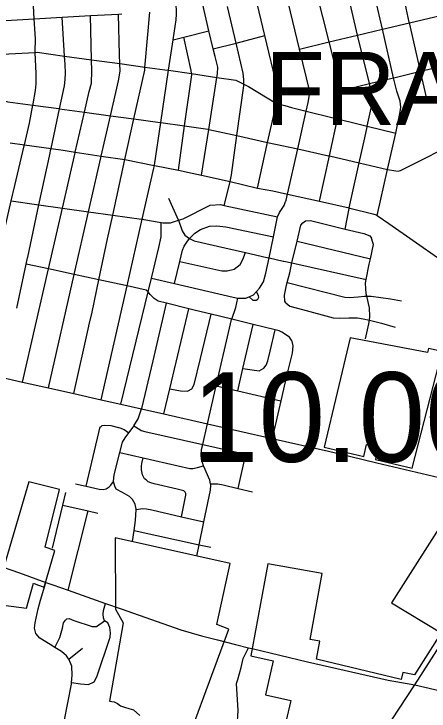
# Model space of a CAD drawing. Extents: x 1659811 to 1934326, y 644115 to 934867.
# Drawn here: x 1806134 to 1811230, y 699875 to 708432 of the extents above; entities that cross this region are included whole.
import ezdxf

# ---------------------------------------------------------------- set-up
doc = ezdxf.new("R2010")
doc.units = 0
for name, color, linetype in [('Default', 7, 'Continuous'), ('GM_X_City_Street', 7, 'Continuous'), ('GM_X_Corporation', 7, 'Continuous'), ('GM_X_County_Road', 7, 'Continuous'), ('GM_X_Township_Text', 7, 'Continuous'), ('GM_X_US_Route', 7, 'Continuous')]:
    doc.layers.add(name, color=color, linetype=linetype)

msp = doc.modelspace()

# ---------------------------------------------------------------- linework, layer by layer
at = {"layer": 'GM_X_City_Street'}
for points in [[(1809469.5, 706130), (1809470.5, 706132.6), (1809476.6, 706148), (1809493.1, 706221), (1809618.1, 706774.9), (1809722.9, 707239), (1809747.3, 707347.2), (1809763.4, 707438), (1809764.4, 707482.2), (1809638.9, 708001.1), (1809446.6, 708801.4), (1809436.2, 708962.9), (1809402, 709522.5), (1809362.2, 710340.5), (1809325.9, 711086.3), (1809295.4, 711711.7), (1809260.4, 712456.7), (1809250.3, 712638.9)], [(1810250.2, 706050.6), (1810371.9, 706604.5), (1810439.5, 706912.4), (1810468.3, 707047.1), (1810469.8, 707053.9), (1810526, 707312.5), (1810531.5, 707368.8), (1810529, 707430.9), (1810507.9, 707539.1), (1810498.6, 707577), (1810352.9, 708171.1), (1810167.1, 708970.7), (1810118.9, 709562.3), (1810067.6, 710366.2), (1810067.4, 710370.1), (1810046.9, 711172.8), (1810010.5, 711774.3), (1809977.9, 712491.9), (1809970.4, 712682.5)], [(1808130, 708430.2), (1808130.8, 708488), (1808122.4, 708568.2), (1808073, 709447.5), (1808038.1, 710255.1), (1808036.4, 710292.2), (1808003.3, 711024.4), (1807975.6, 711638.4), (1807936.9, 712341.2), (1807933.8, 712562.4)], [(1809885.1, 706132.7), (1810005.7, 706689.6), (1810104.2, 707144.5), (1810142.7, 707322.1), (1810155.4, 707432.2), (1810151.8, 707493.4), (1810151.1, 707504.5), (1810005.5, 708088.4), (1809848.5, 708706.8), (1809807.8, 708886.5), (1809793, 709106.1), (1809765.2, 709542.6), (1809723.4, 710336.8), (1809723.1, 710343.3)], [(1809638.9, 708001.1), (1810005.5, 708088.4), (1810352.9, 708171.1), (1810658.7, 708243.9), (1810988, 708322.3), (1811300, 708396.6), (1811615.4, 708471.7), (1812093.2, 708585.5), (1812657.1, 708719.7), (1812940.3, 708787.1), (1813257.9, 708862.8), (1813551, 708932.5), (1813844.2, 709002.4), (1814122.3, 709068.6), (1814126.3, 709069.6), (1814407, 709145.9), (1814414.6, 709147.5), (1814436, 709152.1)], [(1811203.3, 707388.4), (1811125, 707728), (1810988, 708322.3), (1810985.6, 708332.8), (1810949.7, 708504.3), (1810927.3, 708657.3), (1810892.8, 708856.1), (1810837.3, 709094.8), (1810829.4, 709130.4), (1810828.6, 709139.1)], [(1806382.7, 708373.8), (1806361.9, 708776.6)], [(1809121.8, 706294.3), (1809248.6, 706853.5), (1809356.4, 707334.5), (1809379.2, 707446.5), (1809378.8, 707472.2), (1809365.4, 707539.5), (1809213.8, 708167.7), (1809098.6, 708650.1), (1809088, 708689.4), (1809081.8, 708712.6)], [(1810591.1, 705958.6), (1810719.6, 706523.8), (1810820.5, 706967), (1810875.4, 707231.5), (1810884.9, 707287.8), (1810876.3, 707359.9), (1810835.1, 707483.9), (1810804, 707598), (1810792.7, 707647.9), (1810658.7, 708243.9), (1810574.3, 708619.2)], [(1808436.7, 706454.3), (1808525.4, 707014.8), (1808626.6, 707654.1), (1808633.6, 707698.3), (1808635.6, 707778.5), (1808604.7, 707911.6), (1808581.5, 708005.2), (1808527.1, 708224.5), (1808448.1, 708562.7), (1808446.4, 708569.5)], [(1808713.5, 706082.1), (1808787.7, 706370.1), (1808789, 706376.8), (1808803.9, 706456), (1808870.5, 706939.2), (1808954.9, 707551.9), (1808955.4, 707571), (1808956.8, 707628.1), (1808948.7, 707706.6), (1808863, 708074.4), (1808755.6, 708524.3)], [(1807606, 707144.2), (1807606, 707144.2), (1807739.8, 707741.9), (1807742.3, 707781.1), (1807744.7, 707818), (1807802.7, 708452.9)], [(1802838.7, 708169.5), (1802858.4, 708170.7), (1803206.5, 708189.8), (1803531.1, 708211.5), (1803858.4, 708229.7), (1804775.1, 708283.5), (1805404.4, 708317.3), (1805677, 708333), (1805867.1, 708344.3), (1806036.3, 708353.8), (1806382.7, 708373.8), (1806727.9, 708392.6), (1807075.3, 708413.2), (1807419.1, 708431.3), (1807458.3, 708433.7)], [(1806369.5, 707328.4), (1806399.7, 707490.7), (1806408.7, 707572.8), (1806406.2, 707703.2), (1806393.4, 707960.1), (1806393.2, 707966), (1806396.8, 708127.3), (1806382.7, 708373.8)], [(1806577.3, 706724.3), (1806584.1, 706755.9), (1806589.3, 706780), (1806694.3, 707269.6), (1806754.8, 707551.7), (1806764.6, 707625.7), (1806766.5, 707703.9), (1806761.1, 707812.4), (1806754.4, 707915.8), (1806727.9, 708392.6)], [(1806884.5, 706726.4), (1806884.6, 706726.7), (1806886.8, 706736.4), (1806999.5, 707227.6), (1807057.9, 707482), (1807084.5, 707583.7), (1807090.2, 707736.1), (1807086.2, 707870.5), (1807075.3, 708413.2)], [(1807200.9, 706667.1), (1807201.8, 706670.7), (1807205.7, 706688.1), (1807318.6, 707183.7), (1807416.1, 707611.7), (1807439, 707729.6), (1807435.7, 707822.9), (1807431.9, 707932.4), (1807419.1, 708431.3)], [(1807852, 706541.4), (1807858.9, 706571.8), (1807860.2, 706577.5), (1807937.3, 707098.6), (1808032.5, 707741.1), (1808087.9, 708115.5), (1808124.3, 708360.9), (1808129.9, 708429), (1808130, 708430.2)], [(1808087.9, 708115.5), (1808220.1, 708148.3), (1808527.1, 708224.5)], [(1808153.6, 706513.2), (1808229.3, 707057.4), (1808316.4, 707684), (1808313.8, 707699.9), (1808307.7, 707738.3), (1808220.1, 708148.3)], [(1808581.5, 708005.2), (1808863, 708074.4), (1809213.8, 708167.7)], [(1810814.6, 707653.2), (1810815.1, 707653.3), (1811125, 707728), (1811442.4, 707804.6), (1811753.4, 707879.6), (1812224, 707993), (1812752.1, 708120.3)], [(1805707.8, 707925.6), (1806072.4, 707944), (1806393.4, 707960.1), (1806419.3, 707961.4), (1806754.4, 707915.8), (1807086.2, 707870.5), (1807435.7, 707822.9), (1807742.3, 707781.1), (1807987.9, 707747.6), (1808032.5, 707741.1), (1808313.8, 707699.9), (1808626.6, 707654.1), (1808855.9, 707620.5), (1808955.4, 707571), (1809014.3, 707541.7), (1809356.4, 707334.5), (1809461.1, 707306.7), (1809539.9, 707284.3), (1809722.9, 707239), (1810050.9, 707157.7), (1810060.6, 707155.3)], [(1810151.8, 707493.4), (1810498.6, 707577), (1810792.7, 707647.9), (1810814.6, 707653.2)], [(1804712.6, 707421.2), (1805304.8, 707430.5), (1805701.8, 707436.7), (1805729, 707435.6), (1805784, 707433.4), (1806058.5, 707353.2), (1806366.4, 707312.8)], [(1806260, 706815.5), (1806262.6, 706826.4), (1806325.1, 707090.5), (1806366.6, 707312.8), (1806369.1, 707326.5), (1806369.5, 707328.4)], [(1807606, 707144.2), (1807927.1, 707100), (1807937.3, 707098.6), (1808229.3, 707057.4), (1808514.9, 707017.1), (1808525.4, 707014.8), (1808870.5, 706939.2), (1809248.6, 706853.5), (1809618.1, 706774.9), (1809996.7, 706691.7), (1810005.7, 706689.6), (1810371.9, 706604.5), (1810719.6, 706523.8), (1810819.9, 706506.6), (1810850, 706502.9), (1810880, 706511.2), (1811659, 706904.2), (1811962.6, 707005.7), (1812095.4, 707050.1), (1812427.5, 707165.1), (1812952.3, 707346.9)], [(1806366.4, 707312.8), (1806366.6, 707312.8), (1806366.6, 707312.8), (1806683.2, 707271.2), (1806694.3, 707269.6), (1806999.5, 707227.6), (1807318.6, 707183.7), (1807606, 707144.2)], [(1810060.6, 707155.3), (1810104.2, 707144.5), (1810357.4, 707081.8), (1810469.8, 707053.9), (1810820.5, 706967)], [(1807055.1, 704601.7), (1807055.3, 704602.5), (1807093.3, 704773.8), (1807177.3, 705170.5), (1807283.8, 705673.9), (1807346.7, 705963.5), (1807494.7, 706644.4), (1807606, 707144.2)], [(1805948.8, 705487.2), (1806100.3, 706138.1), (1806144.2, 706326.6), (1806259.5, 706813.7), (1806260, 706815.5)], [(1806087.6, 706851.3), (1806262.6, 706826.4), (1806589.3, 706780), (1806737.7, 706758.9), (1806886.8, 706736.4), (1807205.7, 706688.1), (1807494.7, 706644.4)], [(1806239.1, 703913.6), (1806558, 705303.4), (1806729.3, 706050), (1806884.5, 706726.4)], [(1806301.2, 705436.9), (1806303.4, 705447.1), (1806441.3, 706090.3), (1806577.3, 706724.3)], [(1806557.7, 703842.4), (1806874.9, 705235.4), (1807050.2, 706005), (1807200.9, 706667.1)], [(1807494.7, 706644.4), (1807856.6, 706572.3)], [(1807856.6, 706572.3), (1807858.9, 706571.8), (1807859.3, 706571.8), (1808153.6, 706513.2), (1808319.9, 706480), (1808436.7, 706454.3), (1808789, 706376.8), (1809121.8, 706294.3), (1809310.3, 706262.1), (1809493.1, 706221), (1809885.1, 706132.7), (1810250.2, 706050.6), (1810258.7, 706048.6), (1810538.2, 705977.2), (1810582.1, 705964.7), (1810582.7, 705964.3)], [(1807204.5, 703696.9), (1807522.8, 705095.5), (1807708.9, 705912.7), (1807851.9, 706541.2), (1807852, 706541.4)], [(1806099.6, 706138.2), (1806100.3, 706138.1), (1806441.3, 706090.3), (1806729.3, 706050), (1807050.2, 706005), (1807346.7, 705963.5), (1807701.6, 705913.7), (1807708.9, 705912.7), (1807717.2, 705911.5), (1807730.5, 705909.3)], [(1808156, 705899.4), (1808036.7, 706167.8)], [(1809076.7, 704984), (1809110.2, 705024), (1809147.1, 705067.9), (1809195.7, 705143.4), (1809225.4, 705248.5), (1809265.3, 705438.4), (1809319.2, 705695), (1809370.8, 705940.7), (1809395.7, 705995.5), (1809450, 706081.1), (1809469.5, 706130)], [(1807730.5, 705909.3), (1807939.8, 705872.9), (1807963.1, 705868.9), (1808055.4, 705869), (1808156, 705899.4), (1808213, 705916.7), (1808542.5, 706086.8), (1808668.8, 706091.7), (1808713.5, 706082.1), (1809370.8, 705940.7)], [(1810200.2, 705792.3), (1810249.2, 706045.5), (1810250.2, 706050.6)], [(1810582.7, 705964.3), (1810591.1, 705958.6), (1810735, 705860.7), (1811674.4, 705206.2), (1812217.4, 704801.4), (1812401.4, 704707.6), (1812492, 704675.2), (1812669, 704628.6), (1812760.6, 704607.6), (1812860.2, 704584.6)], [(1807446.9, 703641.9), (1807780.7, 705022.8), (1807820.9, 705189.2), (1807911.7, 705564.8), (1807940.9, 705694.6), (1807940.8, 705770.8), (1807939.8, 705872.9)], [(1808156, 705899.4), (1808199.5, 705768.5), (1808232.2, 705715.5), (1808289.5, 705676), (1808346.9, 705646.5), (1808721.9, 705563.1), (1808977.2, 705502.6), (1809236.6, 705444.8), (1809243.9, 705443.2)], [(1809471.5, 704884.5), (1809458, 704906.9), (1809455.8, 704981.2), (1809476.4, 705083.1), (1809489, 705135), (1809518.7, 705256.6), (1809547, 705375.6), (1809610.4, 705642), (1809657.3, 705839.1), (1809680, 705866.7), (1809713.1, 705892.2)], [(1809713.1, 705892.2), (1809775.3, 705897.6), (1810200.2, 705792.3), (1810429.3, 705735.6), (1810502.2, 705709.1), (1810524.9, 705681.5)], [(1808289.5, 705676), (1808353.2, 705740.6), (1808422.5, 705787.1), (1808535.8, 705826.4), (1808626.1, 705830.3), (1808734.1, 705817.6), (1809319.2, 705695)], [(1808103, 705123.8), (1808169.9, 705394.8), (1808203.7, 705531.6), (1808223, 705581.3), (1808256.3, 705632.6), (1808289.5, 705676)], [(1809610.4, 705642), (1810510, 705426.1)], [(1810450.4, 704445.7), (1810490.1, 704626.8), (1810497.3, 704672), (1810504.4, 704716.8), (1810497, 704825.3), (1810465.3, 704968.5), (1810459, 704996.8), (1810448.2, 705127.5), (1810457.4, 705172.6), (1810496, 705361.1), (1810510, 705426.1), (1810548, 705602.6), (1810538.6, 705626.9), (1810524.9, 705681.5)], [(1808169.9, 705394.8), (1808687, 705281), (1808751.1, 705277.4), (1808837.8, 705299.3), (1808909.4, 705357.8), (1808945, 705419.1), (1808977.2, 705502.6)], [(1809243.9, 705443.2), (1809265.3, 705438.4), (1809440, 705399.4), (1809446.1, 705398.1)], [(1806168.7, 704818.9), (1806285.2, 705362), (1806301.2, 705436.9)], [(1808364.7, 704793.7), (1808282.2, 704813.9), (1808008.1, 704881.1), (1807905.7, 704908.8), (1807856.4, 704940.1), (1807805.4, 704987.5), (1807780.7, 705022.8), (1807758.6, 705042.8), (1807522.8, 705095.5), (1807425.5, 705117.2), (1807177.3, 705170.5), (1806874.9, 705235.4), (1806558, 705303.4), (1806285.2, 705362)], [(1809446.1, 705398.1), (1809547, 705375.6), (1810457.4, 705172.6)], [(1807820.9, 705189.2), (1808103, 705123.8), (1808823.4, 704956.6), (1808882.5, 704943.6), (1808979.6, 704944.7), (1809008, 704956.1), (1809022.3, 704961.9), (1809076.7, 704984)], [(1809489, 705135), (1810195.3, 704955.1), (1810247.3, 704949.8), (1810359.8, 704959.1), (1810436.3, 704969.3), (1810465.3, 704968.5), (1810520.5, 704967.2), (1810756.4, 704935.3), (1810890.1, 704912)], [(1809022.3, 704961.9), (1809067.2, 704918.5), (1809109.3, 704917.5), (1809127.7, 704933.1), (1809138.3, 704956.9), (1809134.7, 704973), (1809110.2, 705024)], [(1808377.3, 701777.5), (1808406.5, 701917.8), (1808464.5, 702196.2), (1808546.1, 702587.8), (1808549.7, 702648.1), (1808546, 702666.2), (1808537.2, 702710.3), (1808463.8, 702878.5), (1808461.5, 702885.7), (1808435.1, 702968.6), (1808432.8, 703018.8), (1808438.3, 703087.1), (1808451.4, 703147.6), (1808467.4, 703221.9), (1808509.2, 703401.7), (1808617.1, 703866), (1808806.2, 704680.1), (1808807.9, 704685.2), (1808857.2, 704831), (1808882.5, 704943.6)], [(1807589.4, 701958), (1807608.2, 702089.8), (1807626.3, 702216.3), (1807633.1, 702348.6), (1807633.4, 702352.9), (1807620.9, 702417), (1807588.4, 702471), (1807552.1, 702509), (1807465.5, 702556.6), (1807389, 702600.2), (1807370.7, 702636.3), (1807355.7, 702692.8), (1807354.2, 702698.4), (1807363.7, 702776.8), (1807434.6, 703049.8), (1807467.2, 703175.1), (1807498.9, 703227.5), (1807545.3, 703291), (1807596.2, 703360.7), (1807606.5, 703377.8), (1807657.7, 703463.5), (1807701.4, 703584.3), (1807702.9, 703588.3), (1807843.2, 704175.6), (1808008.1, 704881.1)], [(1809471.5, 704884.5), (1809518.7, 704845.2), (1809674.2, 704805.3), (1810050.7, 704703.8), (1810134.9, 704699.7), (1810243.3, 704703.1), (1810351.5, 704700.4), (1810421.5, 704690.7), (1810497.3, 704672), (1810646.7, 704635), (1810814.1, 704588.8)], [(1807975.4, 703522.2), (1808048.8, 703831.6), (1808282.2, 704813.9)], [(1809421.7, 704526.4), (1809421.3, 704526.6), (1809389, 704541.4), (1809341.2, 704553.7), (1809069.2, 704621.2), (1808807.9, 704685.2), (1808555.1, 704747.1), (1808364.7, 704793.7)], [(1808048.8, 703831.6), (1808177.7, 703806.6), (1808263.8, 703800.5), (1808318.7, 703831.2), (1808346.1, 703884.7), (1808424, 704203.9), (1808555.1, 704747.1)], [(1806871, 703772.4), (1807055.1, 704601.7)], [(1808881.2, 703805.3), (1808944.8, 704081.1), (1809069.2, 704621.2)], [(1808944.8, 704081.1), (1809058.4, 704061.9), (1809142.3, 704051.8), (1809201.3, 704082.5), (1809232.2, 704119.9), (1809249.6, 704173.6), (1809278.6, 704293.3), (1809341.2, 704553.7)], [(1809540.6, 704429.3), (1809515.4, 704464.1), (1809483.9, 704486.9), (1809444.5, 704516), (1809421.7, 704526.4)], [(1809540.6, 704429.3), (1809559, 704358.7), (1809548.8, 704268.6), (1809484.2, 704005.4), (1809409.4, 703683.9), (1809302.1, 703222.6)], [(1804586.6, 704386.7), (1804884.4, 704291.4), (1805625.6, 704054.1), (1806239.1, 703913.6), (1806557.7, 703842.4), (1806871, 703772.4), (1807204.5, 703696.9), (1807446.9, 703641.9), (1807701.4, 703584.3), (1807975.4, 703522.2), (1808509.2, 703401.7), (1809302.1, 703222.6), (1809996.4, 703066.2), (1810269.2, 703000.7), (1810590.2, 702923.5), (1811351.9, 702740.4), (1811573.5, 702687.1), (1812482.7, 702469.2)], [(1808617.1, 703866), (1808881.2, 703805.3), (1809409.4, 703683.9)], [(1807020.3, 702636), (1807193.2, 703364), (1807199.2, 703366.1), (1807217.1, 703380.3)], [(1807217.1, 703380.3), (1807245.1, 703386.5), (1807323.4, 703379), (1807435.9, 703351.6), (1807488.2, 703329.9), (1807545.3, 703291)], [(1807606.5, 703377.8), (1807678.6, 703331.1), (1807694.8, 703319.2), (1807739, 703307.4), (1808451.4, 703147.6), (1808982.1, 703030.5)], [(1807434.6, 703049.8), (1807721.1, 702983.4), (1808291.6, 702851.2), (1808329.7, 702853.5), (1808387.7, 702865.9), (1808461.5, 702885.7)], [(1808192, 702260.4), (1808243.7, 702525.6), (1808243.6, 702547.7), (1808237.5, 702563.7), (1808221.3, 702579.7), (1808139, 702597.2), (1807853.8, 702663.6), (1807813.6, 702675.4), (1807783.4, 702687.2), (1807755.2, 702713.1), (1807735, 702725), (1807710.6, 702773.1), (1807700.2, 702835.2), (1807701.8, 702881.4), (1807705.6, 702913.6), (1807721.1, 702983.4)], [(1808886.4, 702608.5), (1808982.1, 703030.5)], [(1806889.3, 702665.2), (1807020.3, 702636), (1807178.5, 702600.9), (1807230.7, 702593.1), (1807266.7, 702603.5), (1807302.6, 702625.8), (1807322.5, 702648), (1807355.7, 702692.8)], [(1808546, 702666.2), (1808605.7, 702666.5), (1808635.8, 702664.7), (1808704, 702651.1), (1808886.4, 702608.5), (1809063.5, 702567.2)], [(1806608, 701876.2), (1806734.4, 702402.7), (1806771.7, 702558)], [(1806734.4, 702402.7), (1807043.4, 702332.6), (1807162.5, 702305.6)], [(1806799.9, 701360.6), (1807043.4, 702332.6)], [(1807633.1, 702348.6), (1807717.5, 702361.5), (1807759.6, 702359.7), (1807827.9, 702346.1), (1808192, 702260.4), (1808464.5, 702196.2)], [(1807608.2, 702089.8), (1808406.5, 701917.8), (1808549, 701887)], [(1806576.9, 699015), (1806618.5, 699092.5), (1806637.6, 699144.3), (1806642.5, 699170.9), (1806692.4, 699438.8), (1806693.8, 699446.3), (1806751.4, 699746.3), (1806839.3, 700204.1), (1806841.2, 700224.6), (1806849.5, 700314.4), (1806843.7, 700424.9), (1806808.4, 700511), (1806805.5, 700518.1), (1806780.1, 700552.7), (1806719.1, 700606.1), (1806635.5, 700657.5), (1806580.4, 700691.3), (1806453.7, 700770.2), (1806404.8, 700829.4), (1806388, 700892), (1806393.3, 700958.1), (1806430.9, 701130.1), (1806461.1, 701237.8), (1806524.4, 701455.3)], [(1806610.5, 701425.8), (1806799.9, 701360.6), (1807256.5, 701197.2), (1807451.5, 701129.1)], [(1806841.2, 700224.6), (1806953, 700208.4), (1807047.5, 700202.7), (1807119.6, 700235.1), (1807153.5, 700295.4), (1807316.2, 700783.8), (1807320, 700834.1), (1807309.7, 700902.3), (1807287.4, 700956.4), (1807247.3, 700983.3), (1807233.4, 701020.2), (1807227.9, 701063.5), (1807233.4, 701110.5), (1807256.5, 701197.2)], [(1806635.5, 700657.5), (1806663.7, 700713.2), (1806695.5, 700779.6), (1806729.2, 700894.1), (1806743, 700958.4), (1806765, 700992.6), (1806783, 701008.7), (1806813.1, 701010.9), (1806869.5, 700985), (1807094.7, 700913.5), (1807148.9, 700913.7), (1807247.3, 700983.3)], [(1808776.6, 699453), (1808814.4, 699499.4), (1808832.2, 699537.7), (1808843.8, 699591.9), (1808857.3, 699662.3), (1808876.8, 699754.8), (1808884.4, 699811.1), (1808885.9, 699883.4), (1808867.5, 700212.5), (1808881.2, 700264.8), (1808924.3, 700409.7), (1808949.6, 700522.3), (1809013.8, 700652.3)], [(1808852.9, 700692.8), (1809013.8, 700652.3), (1809056.5, 700642)], [(1806808.4, 700511), (1806975.3, 700646.1)]]:
    msp.add_lwpolyline(points, dxfattribs=at)
at = {"layer": 'GM_X_Corporation'}
msp.add_lwpolyline([(1809943.4, 703115.4), (1810427.3, 703000.3), (1810462.2, 703147.2), (1810598.4, 703114.8), (1810573.6, 702964.4), (1811022.8, 702855.1), (1811391.3, 704290), (1811224.7, 704327), (1811211.8, 704278.7), (1810263.2, 704456.4)], close=True, dxfattribs=at)
for points in [[(1805214.9, 701279.4), (1806290, 701140.4), (1806372.3, 701444.9), (1806422, 701426.1), (1806504.5, 701397.3), (1806635.4, 701847.8), (1806516.6, 701886.6), (1806694.7, 702596.6), (1806316.8, 702689.3), (1805994.6, 701587.8)], [(1811523.2, 702387.7), (1810767.7, 701205.9), (1811377.4, 700837.4), (1811049.7, 700319.1), (1810908.4, 700350.7), (1810888.8, 700262.9), (1809847.8, 700512.3), (1809888.3, 700733.6), (1809770.3, 700755.2), (1809918, 701561.9), (1809249.2, 701684.5), (1809042, 700553.1), (1809315.8, 700493), (1809223.6, 700073), (1809531.3, 700005.4), (1809473.4, 699741.7)], [(1808087.8, 699032.6), (1808772.9, 700881.8), (1808624.3, 700936.9), (1808786.8, 701687.6), (1807377.6, 701999.8), (1807380.5, 701124.1), (1807475.7, 700960.4), (1807309.1, 699996.3), (1807363.5, 699987.6), (1807403.6, 699966.2), (1807442.3, 699940.8), (1807490.4, 699924.8), (1807545.1, 699907.4), (1807602.5, 699891.4), (1807678.6, 699819.3)]]:
    msp.add_lwpolyline(points, dxfattribs=at)
at = {"layer": 'GM_X_County_Road'}
for points in [[(1803315.4, 702487.2), (1803764, 702341.4), (1804095.9, 702232.6), (1805138.7, 701916.3), (1805576.6, 701783.6), (1805891, 701680.4), (1806202.7, 701570.6), (1806524.4, 701455.3), (1806610.5, 701425.8)], [(1807451.5, 701129.1), (1808184.7, 700873.1), (1808436.6, 700799.8), (1808633, 700748.2), (1808852.9, 700692.8)], [(1809056.5, 700642), (1809736.6, 700478), (1810729.6, 700255.8), (1811053.4, 700198.6)], [(1811053.4, 700198.6), (1811424.6, 700111.2), (1812105.2, 699957.6), (1812812.6, 699800.9), (1812893.6, 699783), (1812991.3, 699749.8), (1813240.1, 699626.7), (1813369.8, 699562.4), (1813638.2, 699429.6), (1813849.6, 699359), (1814253.3, 699302.2), (1814675.2, 699255.8), (1814681.1, 699255.2), (1815116.7, 699166.4), (1815137.5, 699162.2)]]:
    msp.add_lwpolyline(points, dxfattribs=at)
at = {"layer": 'GM_X_US_Route'}
msp.add_lwpolyline([(1810719.6, 699682.1), (1810774.2, 699767.7), (1811053.4, 700198.6), (1811362, 700675)], dxfattribs=at)

# ---------------------------------------------------------------- texts
at = {"layer": 'Default'}
msp.add_text('10.00', height=1100, dxfattribs=at).set_placement((1808318.6, 702934.4))
at = {"layer": 'GM_X_Township_Text'}
msp.add_text('FRANKLIN', height=900, rotation=0.00001, dxfattribs=at).set_placement((1809215.6, 707067.3))

doc.saveas('drawing.dxf')
